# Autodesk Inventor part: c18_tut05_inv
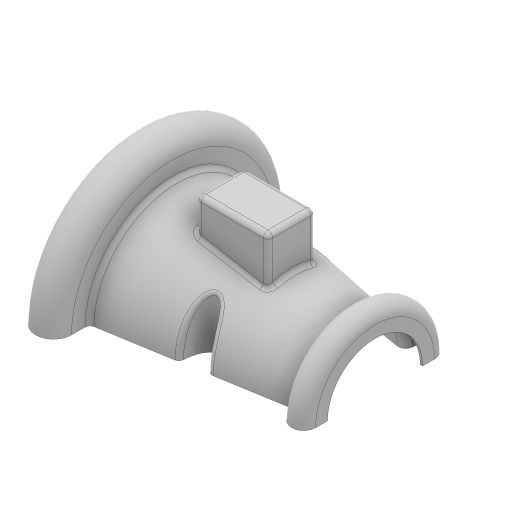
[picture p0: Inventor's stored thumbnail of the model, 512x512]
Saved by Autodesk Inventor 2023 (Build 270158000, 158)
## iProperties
Created: 2017-06
Part Number: c18_tut05_inv
Material: Generic
Document SubType Name: Modeling
Designer: CADCIM 00
Density: 1 g/cm^3
Appearance: Default
Author: CADCIM 00
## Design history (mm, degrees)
sketch "Sketch1"
  geometry: L1 (0, 30)-(0, 42.5); L2 (15, 42.5)-(15, 35); L3 (15, 35)-(90, 22.5); L4 (100, 25)-(100, 20); L5 (90, 25)-(90, 22.5); L6 (0, 0)-(90, 0); A1 r 7.5 centre (7.5, 42.5) between (15, 42.5) and (0, 42.5); A2 r 5 centre (95, 25) between (100, 25) and (90, 25)
  constraints: 12 end point, 4 point on circle, 4 tangent, 2 centre point, 2 parallel, 2 vertical, 2 vertical alignment, 1 horizontal
  dimensions: "d0" = 60 diameter of L1.start L6; "d1" = 70 diameter of L2.end L6; "d2" = 85 diameter of L1.end L6; "d3" = 100 distance between parallel lines of L4 L1; "d4" = 7.5 radius of A1; "d5" = 5 radius of A2; "d6" = 40 diameter of L4.end L6; "d7" = 45 diameter of L3.end L6; "d8" = 50 diameter of L4.start L6
feature "RevolutionSrf1" sketch "Sketch1" dims angle "d9" = 180 deg
sketch "Sketch2" dims "d10" = 5, "d11" = 10
  geometry: L1 (90, 22.5)-(15, 35) reference; 2 further points; 1 other entity
  constraints: 1 midpoint, 2 other
extrude_surface "ExtrusionSrf1" sketch "Sketch2" dims "d12" = 30, "d13" = 0
mirror "Mirror1"
feature "Trim3"
feature "Trim4"
feature "Trim5"
feature "Trim6"
workplane "Work Plane1"
sketch "Sketch3"
  geometry: L1 (35, 10)-(65, 10); L2 (65, 10)-(65, -10); L3 (65, -10)-(35, -10); L4 (35, -10)-(35, 10); 1 further point
  constraints: 8 end point, 2 parallel, 1 horizontal, 1 perpendicular
  dimensions: "d15" = 30 distance of L1.start L1.end; "d16" = 20 distance of L1.end L2.end; "d17" = 10 distance from line of point (0, 0) L3; "d18" = 35 distance from line of L4 point (0, 0)
split "Split1"
delete_face "Delete Face1"
sketch "3D Sketch1"
feature "Stitch Surface1"
fillet "Fillet1" dims "d25" = 2
thicken "Thicken1" dims "d26" = 1
body "Solid1"
body "Srf1"
body "Srf2"
body "Srf3"
node "Edges1"
body "Srf4"
body "Srf5"
body "Srf6"
extrude_surface "ExtrusionSrf2"
feature "LoftSrf1" dims "d19" = 0, "d20" = 90 deg, "d21" = 0, "d22" = 90 deg
patch "Boundary Patch1" dims "d23" = 5, "d24" = 0
other parameters: "d14" = 45
